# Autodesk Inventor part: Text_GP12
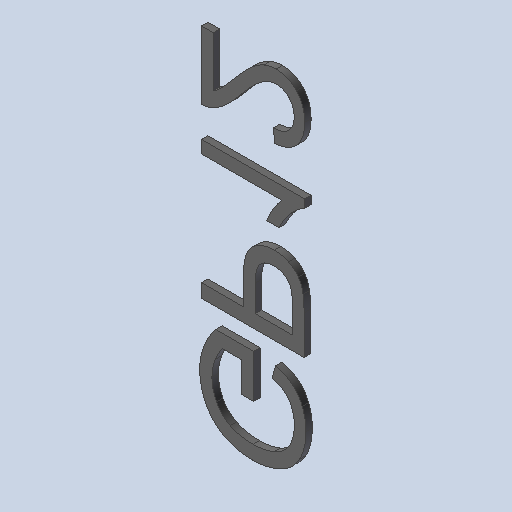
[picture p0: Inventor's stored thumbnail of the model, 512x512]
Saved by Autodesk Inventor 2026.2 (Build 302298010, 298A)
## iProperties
Created: 2026-10
Part Number: Text_GP12
Material: Générique
Document SubType Name: Modeling
Designer: mel
Density: 1 g/cm^3
Appearance: Par défaut
Author: mel
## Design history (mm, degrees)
feature "Base1"
feature "Base2"
feature "Base3"
feature "Base4"
node "Solide1"
node "Solide2"
node "Solide3"
node "Solide4"
